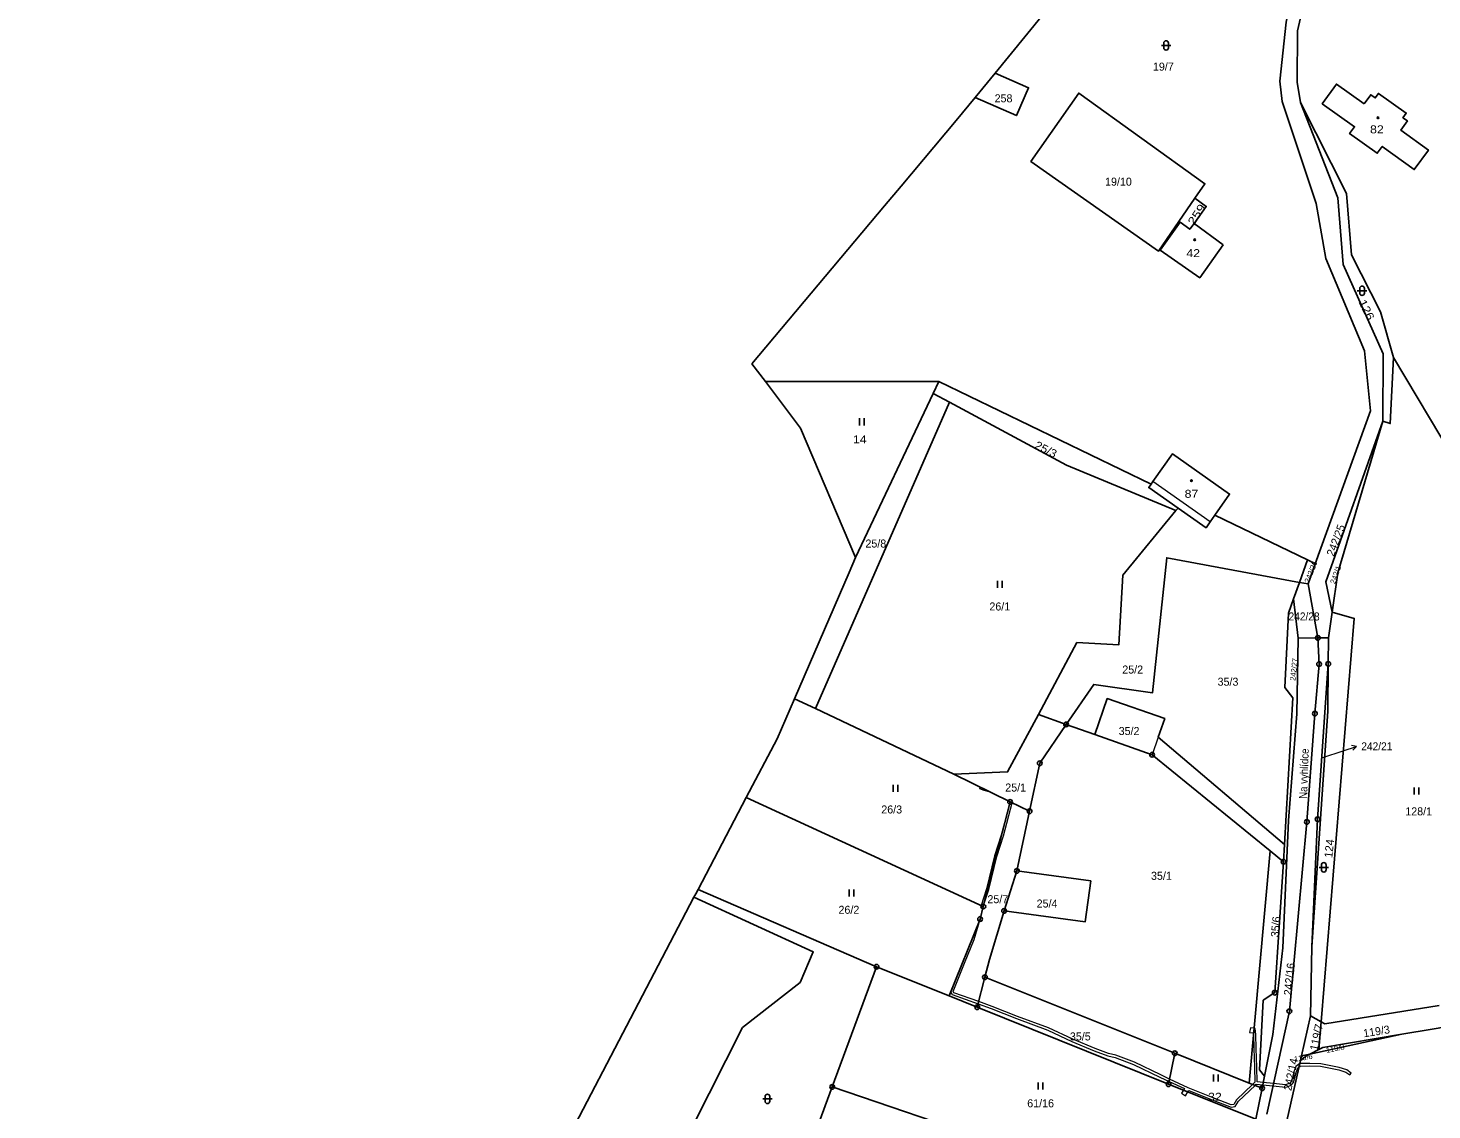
# Model space of a CAD drawing. Extents: x -632162 to -629607, y -1101195 to -1098670.
# Drawn here: x -632123.7 to -631825.5, y -1099165 to -1098935.2 of the extents above; entities that cross this region are included whole.
import ezdxf
from ezdxf.enums import TextEntityAlignment as Align

# ---------------------------------------------------------------- set-up
doc = ezdxf.new("R2010")
doc.units = 0
doc.header["$LTSCALE"] = 0.68
for name, color, linetype, lineweight in [('1', 7, 'Continuous', 25), ('13', 7, 'Continuous', 13), ('3', 7, 'Continuous', 25), ('4', 7, 'Continuous', 13), ('5', 7, 'Continuous', 25), ('7', 7, 'Continuous', 13), ('8', 7, 'Continuous', 25)]:
    doc.layers.add(name, color=color, linetype=linetype, lineweight=lineweight)
doc.layers.add('2', color=7, linetype='Continuous')

msp = doc.modelspace()

# ---------------------------------------------------------------- linework, layer by layer
at = {"layer": '1'}
for p, q in [((-631918.32, -1098944.71), (-631874.52, -1098891.07)), ((-631922.56, -1098949.9), (-631918.32, -1098944.71)), ((-631941.8, -1098972.93), (-631938.26, -1098968.72)), ((-631970, -1099006.47), (-631941.8, -1098972.93)), ((-631875.87, -1098971.32), (-631879.27, -1098976.25)), ((-631879.03, -1098976.43), (-631879.27, -1098976.25)), ((-631869.89, -1098981.24), (-631876.06, -1098976.65)), ((-631967.12, -1099010.29), (-631970, -1099006.47)), ((-631928.01, -1099014.66), (-631956.5, -1099079.76)), ((-631947.97, -1099047.63), (-631931.48, -1099012.8)), ((-631931.48, -1099012.8), (-631928.01, -1099014.66)), ((-631949.35, -1099050.82), (-631947.97, -1099047.63)), ((-631960.94, -1099077.66), (-631949.35, -1099050.82)), ((-631854.93, -1099056.46), (-631853.69, -1099053)), ((-631853.69, -1099053), (-631851.84, -1099053.23)), ((-631853.96, -1099064.78), (-631854.93, -1099056.46)), ((-631849.77, -1099064.73), (-631853.96, -1099064.78)), ((-631847.54, -1099064.71), (-631849.77, -1099064.73)), ((-631960.94, -1099077.66), (-631956.5, -1099079.76)), ((-631956.5, -1099079.76), (-631927.07, -1099093.7)), ((-631903.25, -1099083.13), (-631909.14, -1099081.04)), ((-631903.25, -1099083.13), (-631897.17, -1099085.29)), ((-631883.67, -1099085.81), (-631856.84, -1099108.64)), ((-631981.43, -1099118.19), (-631971.17, -1099098.65)), ((-631915.15, -1099099.6), (-631920.83, -1099121.8)), ((-631864.38, -1099159.32), (-631859.93, -1099109.95)), ((-631856.84, -1099108.64), (-631857.04, -1099112.3)), ((-631981.43, -1099118.19), (-631943.5, -1099134.63)), ((-631920.49, -1099136.84), (-631922.12, -1099143.23)), ((-631880.18, -1099152.99), (-631920.49, -1099136.84)), ((-631922.12, -1099143.23), (-631928.09, -1099140.83)), ((-631881.49, -1099159.57), (-631922.12, -1099143.23)), ((-631851.33, -1099145.02), (-631849.06, -1099146.32)), ((-631849.06, -1099146.32), (-631849.54, -1099152.18)), ((-631851.51, -1099153.18), (-631853.25, -1099153.55)), ((-631851.51, -1099153.18), (-631849.54, -1099152.18)), ((-631861.09, -1099157.84), (-631861.61, -1099160.43)), ((-631868.28, -1099188.89), (-631952.92, -1099160.15))]:
    msp.add_line(p, q, dxfattribs=at)
for points in [[(-631850.34, -1099048.98), (-631838.61, -1099016.51), (-631839.84, -1099003.71), (-631848.05, -1098984.13), (-631850.14, -1098972.45), (-631857.33, -1098950.74), (-631857.87, -1098946.44), (-631856.53, -1098933.93), (-631853.21, -1098916.79), (-631851.18, -1098913.62), (-631836.18, -1098893.82), (-631834.25, -1098891.87), (-631832.69, -1098890.51), (-631822.94, -1098881.98)], [(-631836.9, -1098900.27), (-631849.86, -1098917.35), (-631854.07, -1098935.71), (-631854.14, -1098946.66), (-631853.44, -1098950.94)], [(-631918.32, -1098944.71), (-631911.22, -1098947.83), (-631913.8, -1098953.75), (-631922.56, -1098949.9)], [(-631879.27, -1098976.25), (-631883.63, -1098982.57), (-631910.71, -1098963.5), (-631900.56, -1098948.97), (-631873.75, -1098968.24), (-631875.87, -1098971.32)], [(-631938.26, -1098968.72), (-631926.58, -1098954.83), (-631922.56, -1098949.9)], [(-631833.68, -1099005.17), (-631836.45, -1098995.44), (-631842.61, -1098983.36), (-631843.67, -1098970.31), (-631853.44, -1098950.94)], [(-631853.44, -1098950.94), (-631845.5, -1098971.25), (-631844.39, -1098985.39), (-631835.92, -1099004.38), (-631835.98, -1099018.67)], [(-631875.87, -1098971.32), (-631873.47, -1098973.05), (-631876.06, -1098976.65)], [(-631876.06, -1098976.65), (-631876.97, -1098977.91), (-631879.03, -1098976.43), (-631883.27, -1098982.37)], [(-631883.27, -1098982.37), (-631874.85, -1098988.22), (-631869.89, -1098981.24)], [(-631835.98, -1099018.67), (-631834.39, -1099019.2), (-631833.68, -1099005.17)], [(-631804.98, -1099079.81), (-631815.84, -1099071.64), (-631808.37, -1099047.63), (-631833.68, -1099005.17)], [(-631931.48, -1099012.8), (-631930.28, -1099010.27), (-631967.12, -1099010.29)], [(-631947.97, -1099047.63), (-631959.63, -1099020.19), (-631967.12, -1099010.29)], [(-631930.28, -1099010.27), (-631885.2, -1099032.08), (-631884.8, -1099031.51)], [(-631928.01, -1099014.66), (-631903.17, -1099028), (-631879.92, -1099037.7)], [(-631835.98, -1099018.67), (-631848.1, -1099052.86), (-631846.74, -1099059.27)], [(-631835.98, -1099018.67), (-631845.5, -1099050.9), (-631846.74, -1099059.27)], [(-631884.8, -1099031.51), (-631880.67, -1099025.64), (-631868.51, -1099034.17), (-631871.63, -1099038.64), (-631851.96, -1099048.15), (-631850.34, -1099048.98)], [(-631879.47, -1099037.15), (-631885.69, -1099032.78), (-631885.2, -1099032.08)], [(-631879.92, -1099037.7), (-631891.19, -1099051.44), (-631892.02, -1099066.2), (-631900.94, -1099065.72), (-631909.14, -1099081.04)], [(-631871.63, -1099038.64), (-631872.62, -1099040.06), (-631873.5, -1099041.33), (-631879.47, -1099037.15), (-631879.92, -1099037.7)], [(-631903.25, -1099083.13), (-631897.39, -1099074.61), (-631884.87, -1099076.38), (-631881.88, -1099047.69), (-631853.69, -1099053), (-631851.96, -1099048.15)], [(-631850.34, -1099048.98), (-631851.84, -1099053.23), (-631849.77, -1099064.73)], [(-631856.84, -1099108.64), (-631855.09, -1099077.45), (-631856.78, -1099075.28), (-631856.01, -1099059.49), (-631854.93, -1099056.46)], [(-631849.06, -1099146.32), (-631842.05, -1099060.61), (-631846.74, -1099059.27), (-631847.54, -1099064.71), (-631847.57, -1099070.26)], [(-631853.96, -1099064.78), (-631854.26, -1099080.9), (-631856.01, -1099103.56), (-631857.22, -1099130.61), (-631859.32, -1099148.98), (-631861.09, -1099157.84)], [(-631849.77, -1099064.73), (-631849.52, -1099070.31), (-631850.41, -1099080.83), (-631852.1, -1099103.84), (-631855.83, -1099144.06), (-631860.63, -1099165.93)], [(-631847.57, -1099070.26), (-631847.65, -1099080.31), (-631849.24, -1099103.21), (-631851.03, -1099130.4), (-631851.33, -1099145.02)], [(-631851.03, -1099130.4), (-631849.84, -1099103.28), (-631847.57, -1099070.26)], [(-631971.17, -1099098.65), (-631964.63, -1099086.2), (-631960.94, -1099077.66)], [(-631897.17, -1099085.29), (-631894.49, -1099077.65), (-631882.29, -1099081.87), (-631883.67, -1099085.81)], [(-631909.14, -1099081.04), (-631915.66, -1099093.23), (-631927.07, -1099093.7)], [(-631911.01, -1099101.58), (-631908.85, -1099091.36), (-631903.25, -1099083.13)], [(-631897.17, -1099085.29), (-631884.98, -1099089.56), (-631859.93, -1099109.95), (-631857.04, -1099112.3)], [(-631927.07, -1099093.7), (-631915.15, -1099099.6), (-631911.01, -1099101.58)], [(-631943.5, -1099134.63), (-631928.09, -1099140.83), (-631921.51, -1099124.47), (-631920.83, -1099121.8), (-631971.17, -1099098.65)], [(-631916.42, -1099122.75), (-631913.69, -1099114.26), (-631911.01, -1099101.58)], [(-631857.04, -1099112.3), (-631858.93, -1099140.12), (-631861.41, -1099141.73), (-631862.19, -1099156.55), (-631861.09, -1099157.84)], [(-631913.69, -1099114.26), (-631898, -1099116.37), (-631899.18, -1099125.06), (-631916.42, -1099122.75)], [(-631982.3, -1099119.85), (-631981.9, -1099119.09), (-631981.43, -1099118.19)], [(-632123.73, -1099184.2), (-632102.04, -1099186.98), (-632044.3, -1099194.37), (-632038.8, -1099195.05), (-632022.59, -1099197.06), (-631982.3, -1099119.85)], [(-631982.3, -1099119.85), (-631956.97, -1099131.45), (-631959.75, -1099137.93), (-631972, -1099147.54), (-631986.15, -1099175.57), (-631979.13, -1099188.49), (-631973.64, -1099192.07), (-631962.91, -1099188.51), (-631961.73, -1099183.99), (-631952.92, -1099160.15), (-631943.5, -1099134.63)], [(-631920.49, -1099136.84), (-631919.52, -1099133.06), (-631916.42, -1099122.75)], [(-631823.99, -1099142.85), (-631848.27, -1099146.77), (-631849.06, -1099146.32)], [(-631853.47, -1099154.53), (-631853.25, -1099153.55), (-631851.33, -1099145.02)], [(-631798.56, -1099143.3), (-631825.46, -1099147.85), (-631831.96, -1099148.95), (-631851.51, -1099153.18)], [(-631849.54, -1099152.18), (-631848.75, -1099151.78), (-631831.96, -1099148.95)], [(-631851.51, -1099153.18), (-631852.09, -1099153.47), (-631853.47, -1099154.53), (-631858.39, -1099176.43)]]:
    msp.add_lwpolyline(points, dxfattribs=at)
for points in [[(-631839.95, -1098951.27), (-631838.55, -1098949.31), (-631837.59, -1098949.99), (-631836.9, -1098949.03), (-631831, -1098953.22), (-631831.71, -1098954.2), (-631830.76, -1098954.89), (-631832.17, -1098956.83), (-631826.3, -1098961.09), (-631829.29, -1098965.21), (-631836.08, -1098960.29), (-631837.14, -1098961.75), (-631843.02, -1098957.58), (-631841.98, -1098956.11), (-631848.83, -1098951.24), (-631845.83, -1098947.05)], [(-631881.49, -1099159.57), (-631862.93, -1099167.03), (-631861.61, -1099160.43), (-631864.38, -1099159.32), (-631880.18, -1099152.99)]]:
    msp.add_lwpolyline(points, close=True, dxfattribs=at)
at = {"layer": '13'}
for points in [[(-631919.63, -1099097.38), (-631921.54, -1099096.44), (-631921.66, -1099096.71), (-631920.74, -1099097.1)], [(-631920.83, -1099121.8), (-631915.15, -1099099.6), (-631917.05, -1099106.65), (-631918.46, -1099111.04), (-631920.12, -1099118.03), (-631921.27, -1099121.6)], [(-631920.83, -1099121.8), (-631919.64, -1099118.17), (-631917.98, -1099111.18), (-631916.57, -1099106.79), (-631914.69, -1099099.82), (-631915.15, -1099099.6)], [(-631881.27, -1099158.47), (-631883.1, -1099157.6), (-631888.74, -1099154.92), (-631892.67, -1099153.41), (-631894.26, -1099153.07), (-631897.1, -1099151.99), (-631901.85, -1099150.02), (-631906.96, -1099147.61), (-631913.58, -1099145.16), (-631918.98, -1099143.06), (-631921.81, -1099142.03), (-631927.11, -1099140.14), (-631927.25, -1099139.89), (-631924.84, -1099133.82), (-631922.8, -1099128.83), (-631921.51, -1099124.47), (-631927.75, -1099139.99), (-631927.47, -1099140.54), (-631921.94, -1099142.52), (-631919.16, -1099143.52), (-631913.76, -1099145.62), (-631907.16, -1099148.07), (-631902.05, -1099150.48), (-631897.28, -1099152.45), (-631894.4, -1099153.55), (-631892.81, -1099153.89), (-631888.94, -1099155.38), (-631883.32, -1099158.06), (-631881.37, -1099158.98)], [(-631863.33, -1099147.7), (-631864.1, -1099147.57), (-631864.26, -1099148.56), (-631863.54, -1099148.68), (-631863.46, -1099149.1)], [(-631853.78, -1099155.92), (-631853.62, -1099155.2), (-631854.43, -1099155.8), (-631854.84, -1099156.91), (-631855.4, -1099158.97), (-631855.72, -1099159.36), (-631856.62, -1099159.69), (-631859.2, -1099159.43), (-631861.37, -1099159.21), (-631862.64, -1099159.06), (-631862.7, -1099155.92), (-631862.89, -1099151.98), (-631862.96, -1099149), (-631863.11, -1099147.74), (-631863.33, -1099147.7), (-631863.46, -1099149.1), (-631863.39, -1099152), (-631863.2, -1099155.94), (-631863.14, -1099159.17), (-631863.62, -1099159.62), (-631863.11, -1099159.83), (-631862.84, -1099159.56), (-631861.46, -1099159.7), (-631859.31, -1099159.92), (-631856.6, -1099160.19), (-631856.27, -1099160.12), (-631855.42, -1099159.78), (-631854.94, -1099159.21), (-631854.36, -1099157.07), (-631854.01, -1099156.1)], [(-631853.55, -1099155.73), (-631851.46, -1099155.64), (-631849.22, -1099155.77), (-631845.35, -1099156.5), (-631843.83, -1099157), (-631842.96, -1099157.61), (-631842.67, -1099157.2), (-631843.61, -1099156.54), (-631845.23, -1099156.02), (-631849.16, -1099155.27), (-631851.46, -1099155.14), (-631853.62, -1099155.2), (-631853.78, -1099155.92)], [(-631867.02, -1099162.89), (-631867.65, -1099163.85), (-631868.16, -1099163.93), (-631871.66, -1099162.61), (-631877.34, -1099160.33), (-631881.27, -1099158.47), (-631881.37, -1099158.98), (-631878.13, -1099160.51), (-631878.33, -1099160.84), (-631877.39, -1099161.22), (-631877.21, -1099160.92), (-631871.84, -1099163.07), (-631868.22, -1099164.45), (-631867.35, -1099164.31), (-631866.64, -1099163.21), (-631863.11, -1099159.83), (-631863.62, -1099159.62)], [(-631878.33, -1099160.84), (-631878.74, -1099161.51), (-631877.89, -1099162.03), (-631877.39, -1099161.22)]]:
    msp.add_lwpolyline(points, close=True, dxfattribs=at)
at = {"layer": '3'}
for p, q in [((-631883.001, -1098938.841), (-631880.999, -1098938.841)), ((-631882.501, -1098938.341), (-631882.501, -1098939.342)), ((-631881.499, -1098939.342), (-631881.499, -1098938.341)), ((-631840.891, -1098990.471), (-631840.891, -1098991.472)), ((-631839.889, -1098991.472), (-631839.889, -1098990.471)), ((-631841.391, -1098990.971), (-631839.389, -1098990.971)), ((-631947.121, -1099019.58), (-631947.121, -1099018.08)), ((-631946.12, -1099019.58), (-631946.12, -1099018.08)), ((-631917.841, -1099054.11), (-631917.841, -1099052.61)), ((-631916.84, -1099054.11), (-631916.84, -1099052.61)), ((-631939.991, -1099097.48), (-631939.991, -1099095.98)), ((-631938.99, -1099097.48), (-631938.99, -1099095.98)), ((-631829.291, -1099098.02), (-631829.291, -1099096.52)), ((-631828.29, -1099098.02), (-631828.29, -1099096.52)), ((-631849.011, -1099112.991), (-631849.011, -1099113.992)), ((-631848.009, -1099113.992), (-631848.009, -1099112.991)), ((-631849.511, -1099113.491), (-631847.509, -1099113.491)), ((-631949.331, -1099119.67), (-631949.331, -1099118.17)), ((-631948.33, -1099119.67), (-631948.33, -1099118.17)), ((-631871.941, -1099158.99), (-631871.941, -1099157.49)), ((-631870.94, -1099158.99), (-631870.94, -1099157.49)), ((-631909.171, -1099160.73), (-631909.171, -1099159.23)), ((-631908.17, -1099160.73), (-631908.17, -1099159.23)), ((-631967.691, -1099162.701), (-631965.689, -1099162.701)), ((-631967.191, -1099162.201), (-631967.191, -1099163.202)), ((-631966.189, -1099163.202), (-631966.189, -1099162.201))]:
    msp.add_line(p, q, dxfattribs=at)
for centre, start, end in [((-631882, -1098938.3409), 0, 180), ((-631882, -1098939.3409), 180, 359.98789), ((-631840.39, -1098990.4709), 0, 180), ((-631840.39, -1098991.4709), 180, 359.98789), ((-631848.51, -1099112.9909), 0, 180), ((-631848.51, -1099113.9909), 180, 359.98789), ((-631966.69, -1099162.2009), 0, 180), ((-631966.69, -1099163.2009), 180, 359.98789)]:
    msp.add_arc(centre, 0.5, start, end, dxfattribs=at)
at = {"layer": '4'}
for p, q in [((-631872.62, -1099040.06), (-631884.8, -1099031.51)), ((-631883.67, -1099085.81), (-631884.98, -1099089.56))]:
    msp.add_line(p, q, dxfattribs=at)
at = {"layer": '5'}
for centre in [(-631836.9868, -1098954.2192), (-631875.9468, -1098980.1492), (-631876.6268, -1099031.3192)]:
    msp.add_circle(centre, 0.175, dxfattribs=at)
at = {"layer": '7'}
msp.add_line((-631841.546, -1099087.793), (-631842.653, -1099087.626), dxfattribs=at)
msp.add_lwpolyline([(-631848.7, -1099090.15), (-631844.4, -1099088.72), (-631841.546, -1099087.793), (-631842.344, -1099088.578)], dxfattribs=at)
at = {"layer": '8'}
for centre, radius in [((-631849.77, -1099064.7299), 0.5), ((-631849.77, -1099064.7299), 0.0303), ((-631849.52, -1099070.3099), 0.5), ((-631849.52, -1099070.3099), 0.0303), ((-631847.57, -1099070.2599), 0.5), ((-631847.57, -1099070.2599), 0.0303), ((-631850.41, -1099080.8299), 0.5), ((-631903.25, -1099083.1299), 0.5), ((-631903.25, -1099083.1299), 0.0303), ((-631850.41, -1099080.8299), 0.0303), ((-631884.98, -1099089.5599), 0.5), ((-631908.85, -1099091.3599), 0.5), ((-631908.85, -1099091.3599), 0.0303), ((-631884.98, -1099089.5599), 0.0303), ((-631915.15, -1099099.5999), 0.5), ((-631915.15, -1099099.5999), 0.0303), ((-631911.01, -1099101.5799), 0.5), ((-631911.01, -1099101.5799), 0.0303), ((-631852.1, -1099103.8399), 0.5), ((-631852.1, -1099103.8399), 0.0303), ((-631849.84, -1099103.2799), 0.5), ((-631849.84, -1099103.2799), 0.0303), ((-631857.04, -1099112.2999), 0.5), ((-631857.04, -1099112.2999), 0.0303), ((-631913.69, -1099114.2599), 0.5), ((-631913.69, -1099114.2599), 0.0303), ((-631920.83, -1099121.7999), 0.5), ((-631920.83, -1099121.7999), 0.0303), ((-631921.51, -1099124.4699), 0.5), ((-631921.51, -1099124.4699), 0.0303), ((-631916.42, -1099122.7499), 0.5), ((-631916.42, -1099122.7499), 0.0303), ((-631943.5, -1099134.6299), 0.5), ((-631943.5, -1099134.6299), 0.0303), ((-631920.49, -1099136.8399), 0.5), ((-631920.49, -1099136.8399), 0.0303), ((-631858.93, -1099140.1199), 0.5), ((-631922.12, -1099143.2299), 0.5), ((-631858.93, -1099140.1199), 0.0303), ((-631922.12, -1099143.2299), 0.0303), ((-631855.83, -1099144.0599), 0.5), ((-631855.83, -1099144.0599), 0.0303), ((-631880.18, -1099152.9899), 0.5), ((-631880.18, -1099152.9899), 0.0303), ((-631952.92, -1099160.1499), 0.5), ((-631952.92, -1099160.1499), 0.0303), ((-631881.49, -1099159.5699), 0.5), ((-631881.49, -1099159.5699), 0.0303), ((-631861.61, -1099160.4299), 0.5), ((-631861.61, -1099160.4299), 0.0303)]:
    msp.add_circle(centre, radius, dxfattribs=at)

# ---------------------------------------------------------------- texts
at = {"layer": '2'}
for s, p in [('19/7', (-631882.59, -1098944.2)), ('258', (-631916.539, -1098950.93)), ('19/10', (-631892.13, -1098968.65)), ('25/8', (-631943.66, -1099045.536)), ('26/1', (-631917.33, -1099058.91)), ('25/2', (-631889.1, -1099072.31)), ('35/3', (-631868.86, -1099074.9)), ('35/2', (-631889.87, -1099085.38)), ('25/1', (-631913.96, -1099097.38)), ('26/3', (-631940.29, -1099102.046)), ('128/1', (-631828.36, -1099102.45)), ('35/1', (-631883, -1099116.14)), ('26/2', (-631949.38, -1099123.36)), ('25/7', (-631917.75, -1099121.106)), ('25/4', (-631907.29, -1099122.03)), ('35/5', (-631900.23, -1099150.27)), ('61/16', (-631908.66, -1099164.48))]:
    msp.add_text(s, height=1.7, dxfattribs=at).set_placement(p, align=Align.CENTER)
for s, width, p in [('82', 1.15, (-631837.23, -1098957.53)), ('42', 1.15, (-631876.25, -1098983.83)), ('14', 1.15, (-631947.07, -1099023.4)), ('87', 1.15, (-631876.62, -1099034.97)), ('242/28', 0.95, (-631852.699, -1099061.03)), ('32', 1.15, (-631871.64, -1099163.09))]:
    msp.add_text(s, height=1.7, dxfattribs=dict(at, width=width)).set_placement(p, align=Align.CENTER)
for s, rotation, width, p in [('259', 56, 1.25, (-631874.8009, -1098975.2478)), ('126', 296, 1.2, (-631840.1921, -1098995.3904)), ('25/3', 333, 1.1, (-631907.9179, -1099025.4475)), ('124', 84, 1.05, (-631846.5084, -1099109.5688))]:
    msp.add_text(s, height=1.7, rotation=rotation, dxfattribs=dict(at, width=width)).set_placement(p, align=Align.CENTER)
for s, height, rotation, p in [('242/25', 1.7, 69, (-631845.1583, -1099044.2906)), ('242/26', 1.14, 68, (-631850.723, -1099050.94)), ('242/1', 1.14, 70, (-631845.4664, -1099051.514)), ('242/27', 1.14, 84, (-631854.2981, -1099071.4996)), ('35/6', 1.7, 85, (-631857.8884, -1099126.2041)), ('242/16', 1.7, 84, (-631854.9783, -1099137.3493)), ('119/7', 1.7, 78, (-631849.2533, -1099149.7682)), ('119/3', 1.7, 9, (-631837.1885, -1099149.1752)), ('119/8', 1.14, 12, (-631845.9715, -1099152.5505)), ('242/14', 1.7, 78, (-631854.6927, -1099157.6787)), ('119/6', 1.14, 10, (-631852.7745, -1099154.4894))]:
    msp.add_text(s, height=height, rotation=rotation, dxfattribs=at).set_placement(p, align=Align.CENTER)
at = {"layer": '2', "width": 0.95}
msp.add_text('242/21', height=1.7, dxfattribs=at).set_placement((-631840.55, -1099088.63))
at = {"layer": '7', "width": 0.9}
msp.add_text('Na vyhlídce', height=1.7, rotation=88, dxfattribs=at).set_placement((-631851.8796, -1099093.6197), align=Align.CENTER)

doc.saveas('drawing.dxf')
